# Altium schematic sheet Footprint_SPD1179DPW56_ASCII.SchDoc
size A4; 项目编号: SPSZ2023-052501A; 项目名称: 三相PFC-2.2KW压机+700W风机
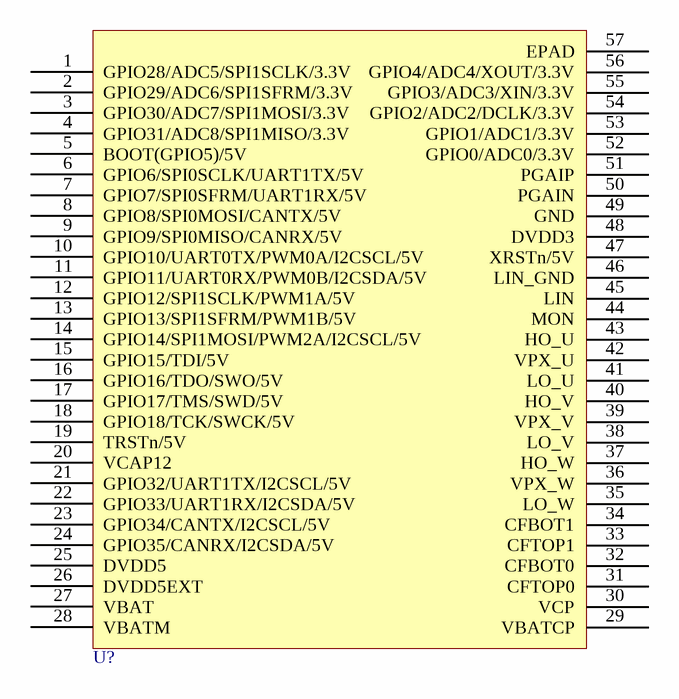
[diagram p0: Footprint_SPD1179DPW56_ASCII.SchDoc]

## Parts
U?  SPD1179  [QFN-56-0.5_B]  (value not drawn)

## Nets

Not connected (* = marked no-connect by the designer): U? 1(GPIO28/ADC5/SPI1SCLK/3.3V) 2(GPIO29/ADC6/SPI1SFRM/3.3V) 3(GPIO30/ADC7/SPI1MOSI/3.3V) 4(GPIO31/ADC8/SPI1MISO/3.3V) 5(BOOT(GPIO5)/5V) 6(GPIO6/SPI0SCLK/UART1TX/5V) 7(GPIO7/SPI0SFRM/UART1RX/5V) 8(GPIO8/SPI0MOSI/CANTX/5V) 9(GPIO9/SPI0MISO/CANRX/5V) 10(GPIO10/UART0TX/PWM0A/I2CSCL/5V) 11(GPIO11/UART0RX/PWM0B/I2CSDA/5V) 12(GPIO12/SPI1SCLK/PWM1A/5V) 13(GPIO13/SPI1SFRM/PWM1B/5V) 14(GPIO14/SPI1MOSI/PWM2A/I2CSCL/5V) 15(GPIO15/TDI/5V) 16(GPIO16/TDO/SWO/5V) 17(GPIO17/TMS/SWD/5V) 18(GPIO18/TCK/SWCK/5V) 19(TRSTn/5V) 20(VCAP12) 21(GPIO32/UART1TX/I2CSCL/5V) 22(GPIO33/UART1RX/I2CSDA/5V) 23(GPIO34/CANTX/I2CSCL/5V) 24(GPIO35/CANRX/I2CSDA/5V) 25(DVDD5) 26(DVDD5EXT) 27(VBAT) 28(VBATM) 29(VBATCP) 30(VCP) 31(CFTOP0) 32(CFBOT0) 33(CFTOP1) 34(CFBOT1) 35(LO_W) 36(VPX_W) 37(HO_W) 38(LO_V) 39(VPX_V) 40(HO_V) 41(LO_U) 42(VPX_U) 43(HO_U) 44(MON) 45(LIN) 46(LIN_GND) 47(XRSTn/5V) 48(DVDD3) 49(GND) 50(PGAIN) 51(PGAIP) 52(GPIO0/ADC0/3.3V) 53(GPIO1/ADC1/3.3V) 54(GPIO2/ADC2/DCLK/3.3V) 55(GPIO3/ADC3/XIN/3.3V) 56(GPIO4/ADC4/XOUT/3.3V) 57(EPAD)

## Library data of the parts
U? = U_SPD1179_QFN56: 32-bit ARM CM4 automotives MCU with HV power management, LIN and PDRV; Manufacture: Spintrol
